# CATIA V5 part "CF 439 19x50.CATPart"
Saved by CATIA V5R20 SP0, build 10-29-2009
Part number: CF 439 19x50
Definition: NONE
Nomenclature: CF 439 19x50
Source: Unknown
Description: CF 439 19x50
Bounding box of the stored display mesh (mm): x -17 to 17, y 0 to 50, z -17 to 17
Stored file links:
  C:\Users\Utente\Desktop\IO LAVORO\3D X SITO CF\X SITO\CF 439\CF 439 19x50.CATPart
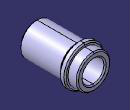
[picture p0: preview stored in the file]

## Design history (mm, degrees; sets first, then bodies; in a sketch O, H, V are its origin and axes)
Body1 "CF 439 19x50" (main body)
  Solid1: solid without history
